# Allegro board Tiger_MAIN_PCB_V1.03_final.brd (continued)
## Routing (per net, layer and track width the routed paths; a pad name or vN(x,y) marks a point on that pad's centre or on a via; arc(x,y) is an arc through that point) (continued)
M_B_DQ<9>: length 61.9
  TOP w0.076: v2(206.19,48.98) 206.75,49.55 206.75,54.39 206.75,54.39 206.75,55.51 206.54,55.71 206.54,56.26 206.22,56.58 U1.AW35
  TOP w0.129: v2(232.86,20.03) 232.77,20.03 232.37,20.44 CN1.29
  LAY3 w0.076: v2(206.19,48.98) 205.77,48.56 205.77,44.45
  LAY3 w0.087: v2(232.86,20.03) 232.47,20.43 232.47,23.89 229.94,26.42 229.57,26.42 228.65,27.35 228.65,27.47 228.8,27.62 228.8,27.74 228.67,27.87 228.55,27.87 228.4,27.72 228.28,27.72 228.16,27.84 228.16,27.96 228.31,28.11 228.31,28.23 228.18,28.36 228.06,28.36 227.91,28.21 227.79,28.21 227.67,28.33 227.67,28.45 227.82,28.6 227.82,28.72 227.69,28.85 227.57,28.85 227.42,28.7 227.3,28.7 227.18,28.82 227.18,28.94 227.33,29.09 227.33,29.22 227.2,29.34 227.08,29.34 226.93,29.19 226.81,29.19 226.69,29.31 226.69,29.43 226.84,29.58 226.84,29.71 226.71,29.83 226.59,29.83 226.44,29.68 226.32,29.68 226.19,29.8 226.19,29.92 226.35,30.07 226.35,30.2 226.22,30.32 226.1,30.32 225.95,30.17 225.83,30.17 225.7,30.29 225.7,30.41 225.86,30.56 225.86,30.69 225.73,30.81 225.61,30.81 225.46,30.66 225.34,30.66 225.21,30.78 225.21,30.9 225.37,31.05 225.37,31.18 225.24,31.3 225.12,31.3 224.97,31.15 224.85,31.15 224.72,31.27 224.72,31.39 224.87,31.54 224.87,31.67 224.75,31.79 224.63,31.79 224.48,31.64 224.36,31.64 224.23,31.76 224.23,31.88 224.38,32.03 224.38,32.16 224.26,32.28 224.14,32.28 223.99,32.13 223.87,32.13 223.74,32.25 223.74,32.37 223.89,32.52 223.89,32.65 223.77,32.77 223.65,32.77 223.5,32.62 223.38,32.62 223.25,32.74 223.25,32.86 223.4,33.01 223.4,33.14 223.28,33.26 223.16,33.26 223.01,33.11 222.89,33.11 222.55,33.45 215.73,33.45 205.77,43.4 205.77,44.45
M_B_DQ<10>: length 61.2
  TOP w0.076: U1.AY33 204.99,55.92 204.72,55.65 204.72,55.3 204.67,55.2 204.61,55.06 204.56,54.97 204.56,54.6 204.69,54.48 204.69,54.48 204.74,54.42 204.74,54.1 204.58,53.94 204.58,51.01 204.02,50.44 204.02,50.44 203.9,50.32 203.9,46.89 v2(204.41,46.38)
  TOP w0.129: CN1.37 230.37,20.13 229.68,19.45 v2(229.36,19.45)
  LAY3 w0.076: v2(204.41,46.38) 204,45.97 204,45.23 203.64,44.87
  LAY3 w0.087: 203.64,44.87 203.64,41.51 206.69,38.46 206.69,37.85 206.83,37.7 206.94,37.7 207.1,37.86 207.22,37.86 207.34,37.73 207.34,37.61 207.2,37.47 207.2,37.34 207.32,37.21 207.45,37.21 207.66,37.43 207.78,37.43 207.91,37.31 207.91,37.18 207.69,36.97 207.69,36.85 207.82,36.72 207.94,36.72 208.15,36.94 208.27,36.94 208.4,36.82 208.4,36.69 208.18,36.48 208.18,36.36 208.31,36.23 208.43,36.23 208.64,36.45 208.76,36.45 208.89,36.33 208.89,36.2 208.67,35.99 208.67,35.87 208.8,35.74 208.92,35.74 209.13,35.96 209.25,35.96 209.38,35.84 209.38,35.71 209.16,35.5 209.16,35.38 209.29,35.25 209.41,35.25 209.62,35.47 209.74,35.47 209.87,35.35 209.87,35.22 209.65,35.01 209.65,34.89 209.78,34.76 209.9,34.76 210.11,34.98 210.24,34.98 210.36,34.85 210.36,34.73 210.14,34.52 210.14,34.4 213.68,30.86 221.57,30.86 228.96,23.46 228.96,19.85 v2(229.36,19.45)
M_B_DQ<11>: length 60.1
  TOP w0.076: U1.AW33 205.65,56.78 205.85,56.57 205.85,56.06 205.92,55.95 205.92,55.7 205.88,55.58 205.88,55.35 205.89,55.34 205.89,55.34 205.89,55.34 205.92,55.25 205.92,55.05 205.89,54.96 205.89,54.29 206.09,54.08 206.09,53.18 205.46,52.55 205.46,50.07 205.59,49.94 205.59,46.91 v2(204.41,45.73)
  TOP w0.129: v2(229.36,20.62) 229.37,20.62 CN1.41
  LAY3 w0.076: v2(204.41,45.73) 204.41,45.31 203.97,44.87
  LAY3 w0.087: v2(229.36,20.62) 229.49,20.74 229.49,21.77 229.41,21.85 229.37,21.85 229.28,21.94 229.28,22.11 229.37,22.2 229.41,22.2 229.49,22.29 229.49,22.46 229.41,22.55 229.37,22.55 229.28,22.63 229.28,22.81 229.37,22.89 229.41,22.89 229.49,22.98 229.49,23.43 221.74,31.19 214.52,31.19 214.18,31.53 214.06,31.53 213.84,31.31 213.72,31.31 213.59,31.43 213.59,31.55 213.81,31.77 213.81,31.89 213.69,32.02 213.57,32.02 213.35,31.8 213.23,31.8 213.1,31.92 213.1,32.04 213.32,32.26 213.32,32.38 213.2,32.51 213.08,32.51 212.86,32.29 212.74,32.29 212.61,32.41 212.61,32.53 212.83,32.75 212.83,32.87 212.71,33 212.59,33 212.37,32.78 212.25,32.78 212.12,32.9 212.12,33.02 212.34,33.24 212.34,33.36 212.22,33.49 212.1,33.49 211.88,33.27 211.76,33.27 211.63,33.39 211.63,33.51 211.85,33.73 211.85,33.85 211.73,33.98 211.61,33.98 211.39,33.76 211.27,33.76 211.14,33.88 211.14,34 211.36,34.22 211.36,34.34 211.24,34.47 211.12,34.47 210.9,34.25 210.78,34.25 210.65,34.37 210.65,34.49 210.87,34.71 210.87,34.83 203.97,41.74 203.97,44.87
M_B_DQ<12>: length 60
  TOP w0.076: v2(206.19,50.93) 205.79,51.32 205.79,52.41 206.42,53.04 206.42,54.25 206.42,54.72 U1.BB35
  TOP w0.129: CN1.24 233.61,15.81 232.51,16.92 v2(232.11,16.92)
  LAY3 w0.076: v2(206.19,50.93) 206.12,50.93 205.42,50.23 205.42,45.08 205.19,44.85 ; 231.2,23.35 231.2,21.32 231.82,20.69
  LAY3 w0.087: 231.82,20.69 231.82,18.41 231.91,18.32 232.79,18.32 232.87,18.24 232.87,18.06 232.79,17.98 231.91,17.98 231.82,17.89 231.82,17.06 231.97,16.92 v2(232.11,16.92) ; 231.2,23.35 231.2,23.91 222.33,32.77 215.45,32.77 205.19,43.04 205.19,44.85
M_B_DQ<13>: length 60.2
  TOP w0.076: U1.BA35 206.32,55.25 206.59,54.99 206.59,54.32 206.59,54.32 206.59,52.63 v2(206.19,52.23)
  TOP w0.129: CN1.28 232.61,15.25 v2(232.11,15.75)
  LAY3 w0.076: 204.88,44.88 205.25,45.25 205.25,51.29 v2(206.19,52.23)
  LAY3 w0.087: v2(232.11,15.75) 231.44,16.43 231.44,17.45 231.35,17.53 230.88,17.53 230.79,17.62 230.79,17.79 230.88,17.88 231.35,17.88 231.44,17.97 231.44,18.14 231.35,18.23 230.88,18.23 230.79,18.31 230.79,18.49 230.88,18.57 231.35,18.57 231.44,18.66 231.44,19.12 230.83,19.73 230.83,23.83 222.22,32.44 215.31,32.44 204.88,42.87 204.88,44.88
M_B_DQ<14>: length 60.4
  TOP w0.076: U1.BA33 204.99,55.33 204.85,55.18 204.85,55.18 204.85,55.18 204.73,54.93 204.73,54.67 204.91,54.49 204.91,54.03 204.77,53.89 204.77,50.64 v2(204.41,50.28)
  TOP w0.129: CN1.42 229.11,15.16 v2(229.11,15.16)
  LAY3 w0.076: 202.98,44.8 203.29,45.11 203.29,49.16 v2(204.41,50.28)
  LAY3 w0.087: v2(229.11,15.16) 228.52,15.16 228.21,15.48 228.21,23.32 221.33,30.2 213.31,30.2 204.78,38.73 204.78,38.85 204.95,39.02 204.95,39.15 204.83,39.27 204.7,39.27 204.53,39.1 204.41,39.1 204.29,39.22 204.29,39.34 204.46,39.51 204.46,39.64 204.34,39.76 204.21,39.76 204.04,39.59 203.92,39.59 203.8,39.71 203.8,39.83 203.97,40 203.97,40.13 203.85,40.25 203.72,40.25 203.55,40.08 203.43,40.08 202.98,40.53 202.98,44.8
M_B_DQ<15>: length 59.6
  TOP w0.076: v2(204.41,49.63) 204.93,50.15 204.93,53.82 205.07,53.96 205.07,54.61 204.99,54.69 U1.BB33
  TOP w0.129: v2(229.11,16.33) 229.39,16.33 230.11,15.61 CN1.38
  LAY3 w0.076: 203.34,44.88 203.61,45.16 203.61,48.83 v2(204.41,49.63)
  LAY3 w0.087: v2(229.11,16.33) 228.84,16.33 228.65,16.53 228.65,17.66 228.73,17.74 229.09,17.74 229.18,17.83 229.18,18 229.09,18.09 228.73,18.09 228.65,18.18 228.65,18.35 228.73,18.44 229.09,18.44 229.18,18.52 229.18,18.7 229.09,18.78 228.73,18.78 228.65,18.87 228.65,23.33 221.42,30.56 213.46,30.56 206.25,37.77 206.25,38.38 203.34,41.29 203.34,44.88
M_B_DQ<16>: length 51.4
  TOP w0.076: U1.AU40 v2(209.76,57.61)
  TOP w0.129: v2(194.62,15.75) 194.11,15.25 CN1.174
  LAY6 w0.076: 207.28,44.39 207.28,52.39 208.9,54.01 208.9,56.75 v2(209.76,57.61) ; 194.06,21.15 194.24,20.96
  LAY6 w0.087: 194.06,21.15 193.93,21.27 193.93,24.39 194.18,24.63 194.18,28.27 197.39,31.48 197.39,32.1 199.52,34.23 199.52,36.13 207.28,43.89 207.28,44.39 ; v2(194.62,15.75) 194.24,16.13 194.24,20.96
M_B_DQ<17>: length 52
  TOP w0.076: U1.AT40 v2(209.76,58.24)
  TOP w0.129: v2(194.86,20.03) 194.36,20.53 CN1.173
  LAY6 w0.076: v2(209.76,58.24) 209.76,58.12 210.11,57.77 210.11,56.8 209.15,55.83 209.15,53.95 207.57,52.37 207.57,44.23
  LAY6 w0.087: v2(194.86,20.03) 194.81,19.97 194.66,19.97 194.48,20.15 194.48,21.24 194.29,21.43 194.29,24.19 194.48,24.38 194.48,28.13 197.77,31.41 197.77,31.99 197.95,32.17 198.07,32.17 198.22,32.02 198.34,32.02 198.47,32.14 198.47,32.26 198.32,32.41 198.32,32.53 198.44,32.66 198.56,32.66 198.71,32.51 198.84,32.51 198.96,32.63 198.96,32.75 198.81,32.9 198.81,33.02 198.93,33.15 199.05,33.15 199.2,33 199.33,33 199.45,33.12 199.45,33.24 199.3,33.39 199.3,33.51 199.84,34.06 199.84,34.61 199.93,34.69 200.41,34.69 200.5,34.78 200.5,34.95 200.41,35.04 199.93,35.04 199.84,35.13 199.84,35.3 199.93,35.39 200.41,35.39 200.5,35.47 200.5,35.65 200.41,35.73 199.93,35.73 199.84,35.82 199.84,36.04 207.57,43.77 207.57,44.23
M_B_DQ<18>: length 53
  TOP w0.076: U1.AT37 v2(207.93,58.24)
  TOP w0.129: CN1.182 192.11,15.34 v2(191.11,16.34)
  LAY6 w0.076: v2(207.93,58.24) 207.93,58.13 207.57,57.77 207.57,56.05 207.12,55.6 207.12,53.92 205.43,52.23
  LAY6 w0.087: 205.43,52.23 205.43,43.91 197.94,36.42 197.94,34.95 191.83,28.84 191.83,21.48 191.63,21.28 191.63,18.18 191.54,18.1 191.33,18.1 191.24,18.01 191.24,17.84 191.33,17.75 191.54,17.75 191.63,17.66 191.63,16.85 v2(191.11,16.34)
M_B_DQ<19>: length 52.4
  TOP w0.076: U1.AU37 v2(207.93,57.59)
  TOP w0.129: CN1.186 v2(191.11,15.17)
  LAY6 w0.076: 205.73,52.28 207.29,53.84 207.29,55.39 207.93,56.03 v2(207.93,57.59)
  LAY6 w0.087: v2(191.11,15.17) 191.94,16 191.94,18.14 192.03,18.23 192.23,18.23 192.32,18.31 192.32,18.49 192.23,18.57 192.03,18.57 191.94,18.66 191.94,18.83 192.03,18.92 192.23,18.92 192.32,19.01 192.32,19.18 192.23,19.27 192.03,19.27 191.94,19.35 191.94,21.13 192.13,21.32 192.13,28.66 198.24,34.77 198.24,36.29 205.73,43.78 205.73,52.28
M_B_DQ<20>: length 52.7
  TOP w0.076: U1.AR40 v2(209.76,58.88)
  TOP w0.129: CN1.169 195.36,19.36 v2(194.86,18.86)
  LAY6 w0.076: v2(209.76,58.88) 210.14,58.5 210.14,57.99 210.28,57.85 210.28,56.64 209.76,56.12 209.76,53.22 208.37,51.83 208.37,46.11 207.88,45.63 207.88,44.29
  LAY6 w0.087: 207.88,44.29 207.88,43.64 200.81,36.57 200.81,34 200.35,33.55 200.23,33.55 200.07,33.7 199.94,33.7 199.82,33.58 199.82,33.46 199.98,33.3 199.98,33.18 194.8,28 194.8,21.6 195.26,21.14 195.26,18.53 195.15,18.42 194.84,18.42 194.71,18.55 194.71,18.71 v2(194.86,18.86)
M_B_DQ<21>: length 53.7
  TOP w0.076: U1.AP40 v2(209.76,59.51)
  TOP w0.129: v2(194.61,16.96) 195.11,16.46 CN1.170
  LAY6 w0.076: v2(209.76,59.51) 210.3,58.97 210.3,58.11 210.44,57.97 210.44,56.33 209.96,55.85 209.96,53.13 208.59,51.76 208.59,46.05 208.09,45.56 208.09,44.27
  LAY6 w0.087: 208.09,44.27 208.09,43.42 201.12,36.44 201.12,33.87 195.12,27.86 195.12,21.84 195.47,21.48 195.47,17.83 v2(194.61,16.96)
M_B_DQ<22>: length 54.5
  TOP w0.076: U1.AP37 v2(207.93,59.51)
  TOP w0.129: CN1.187 190.86,20.62 v2(190.86,20.62)
  LAY6 w0.076: 204.81,52.13 206.69,54 206.69,55.75 207.22,56.28 207.22,57.93 207.37,58.09 207.37,58.95 v2(207.93,59.51)
  LAY6 w0.087: v2(190.86,20.62) 190.86,22.59 190.95,22.68 191.09,22.68 191.18,22.76 191.18,22.94 191.09,23.02 190.95,23.02 190.86,23.11 190.86,23.28 190.95,23.37 191.09,23.37 191.18,23.46 191.18,23.63 191.09,23.72 190.95,23.72 190.86,23.8 190.86,23.98 190.95,24.06 191.09,24.06 191.18,24.15 191.18,24.32 191.09,24.41 190.95,24.41 190.86,24.49 190.86,24.67 190.95,24.75 191.09,24.75 191.18,24.84 191.18,25.01 191.09,25.1 190.95,25.1 190.86,25.19 190.86,25.36 190.95,25.45 191.09,25.45 191.18,25.53 191.18,25.71 191.09,25.79 190.95,25.79 190.86,25.88 190.86,26.05 190.95,26.14 191.09,26.14 191.18,26.23 191.18,26.4 191.09,26.49 190.95,26.49 190.86,26.57 190.86,26.75 190.95,26.83 191.09,26.83 191.18,26.92 191.18,27.09 191.09,27.18 190.95,27.18 190.86,27.27 190.86,27.44 190.95,27.53 191.09,27.53 191.18,27.61 191.18,27.79 191.09,27.87 190.95,27.87 190.86,27.96 190.86,28.13 190.95,28.22 191.09,28.22 191.18,28.31 191.18,28.48 191.09,28.57 190.95,28.57 190.86,28.65 190.86,29.32 191.16,29.62 191.29,29.62 191.44,29.47 191.56,29.47 191.69,29.59 191.69,29.71 191.53,29.87 191.53,29.99 191.65,30.11 191.78,30.11 191.93,29.96 192.05,29.96 192.18,30.08 192.18,30.2 192.02,30.36 192.02,30.48 192.14,30.6 192.27,30.6 192.42,30.45 192.55,30.45 192.67,30.57 192.67,30.69 192.51,30.85 192.51,30.97 192.63,31.09 192.76,31.09 192.91,30.94 193.04,30.94 193.16,31.06 193.16,31.18 193,31.34 193,31.46 196.96,35.42 196.96,35.6 197.04,35.69 197.19,35.69 197.27,35.77 197.27,35.95 197.19,36.03 197.04,36.03 196.96,36.12 196.96,36.3 204.81,44.16 204.81,52.13
M_B_DQ<23>: length 54.1
  TOP w0.076: U1.AR37 v2(207.93,58.88)
  TOP w0.129: CN1.183 191.86,19.85 191.47,19.45 v2(190.86,19.45)
  LAY6 w0.076: v2(207.93,58.88) 207.56,58.51 207.56,58.01 207.4,57.84 207.4,56.17 206.9,55.67 206.9,53.95 205.12,52.17
  LAY6 w0.087: v2(190.86,19.45) 191.3,19.88 191.3,21.55 191.51,21.76 191.51,28.98 193.97,31.44 193.97,31.56 193.83,31.7 193.83,31.82 193.95,31.94 194.07,31.94 194.21,31.8 194.33,31.8 194.46,31.93 194.46,32.05 194.32,32.19 194.32,32.31 194.44,32.43 194.56,32.43 194.7,32.29 194.82,32.29 194.95,32.42 194.95,32.54 194.81,32.68 194.81,32.8 194.93,32.92 195.05,32.92 195.19,32.78 195.31,32.78 195.44,32.91 195.44,33.03 195.3,33.17 195.3,33.29 195.42,33.41 195.54,33.41 195.68,33.27 195.81,33.27 195.93,33.4 195.93,33.52 195.79,33.66 195.79,33.78 195.91,33.9 196.03,33.9 196.17,33.76 196.3,33.76 196.42,33.89 196.42,34.01 196.28,34.15 196.28,34.27 196.4,34.39 196.53,34.39 196.66,34.25 196.79,34.25 196.91,34.38 196.91,34.5 196.77,34.64 196.77,34.76 196.89,34.88 197.02,34.88 197.1,34.79 197.33,34.79 197.63,35.1 197.63,36.55 205.12,44.04 205.12,52.17
M_B_DQ<24>: length 55.2
  TOP w0.076: v2(206.1,58.24) 205.92,58.38 U1.AT33
  TOP w0.129: v2(189.36,18.86) 189.87,19.36 CN1.191
  LAY6 w0.076: v2(206.1,58.24) 206.1,58.13 206.46,57.78 206.46,57.31 205.85,56.71 205.85,54.89 204.5,53.54 204.5,52.99 203.54,52.03
  LAY6 w0.087: v2(189.36,18.86) 189.75,18.86 189.96,19.07 189.96,20.98 189.8,21.14 189.8,30.08 192.97,33.25 192.97,34.23 193.19,34.46 193.31,34.46 193.62,34.15 193.74,34.15 193.86,34.28 193.86,34.4 193.56,34.7 193.56,34.82 193.68,34.95 193.8,34.95 194.11,34.64 194.23,34.64 194.35,34.77 194.35,34.89 194.05,35.19 194.05,35.31 194.17,35.44 194.29,35.44 194.6,35.13 194.72,35.13 194.84,35.26 194.84,35.38 194.54,35.68 194.54,35.8 194.66,35.93 194.78,35.93 195.09,35.62 195.21,35.62 195.33,35.75 195.33,35.87 195.03,36.17 195.03,36.29 198.72,39.99 199.27,39.99 203.54,44.25 203.54,52.03
M_B_DQ<25>: length 54.7
  TOP w0.076: v2(206.1,57.61) 205.92,57.74 U1.AU33
  TOP w0.129: CN1.195 188.87,20.53 v2(189.36,20.03)
  LAY6 w0.076: 203.32,52.1 204.27,53.06 204.27,53.64 205.57,54.94 205.57,56.75 206.1,57.28 v2(206.1,57.61)
  LAY6 w0.087: 203.32,52.1 203.32,44.45 199.23,40.36 198.65,40.36 192.25,33.96 192.25,33.84 192.55,33.54 192.55,33.41 192.43,33.29 192.31,33.29 192.01,33.59 191.88,33.59 191.76,33.47 191.76,33.35 192.11,32.99 192.11,32.87 191.99,32.75 191.87,32.75 191.52,33.1 191.39,33.1 191.27,32.98 191.27,32.86 191.62,32.5 191.62,32.38 191.5,32.26 191.38,32.26 191.03,32.61 190.9,32.61 190.78,32.49 190.78,32.37 191.13,32.01 191.13,31.89 191.01,31.77 190.89,31.77 190.54,32.12 190.41,32.12 190.29,32 190.29,31.88 190.64,31.52 190.64,31.4 190.52,31.28 190.4,31.28 190.05,31.63 189.92,31.63 189.8,31.51 189.8,31.39 190.15,31.03 190.15,30.91 190.03,30.79 189.91,30.79 189.55,31.14 189.43,31.14 189.26,30.97 189.26,21.25 189.74,20.77 189.74,20.41 v2(189.36,20.03)
M_B_DQ<26>: length 53.7
  TOP w0.076: U1.AU30 v2(204.28,57.61)
  TOP w0.129: CN1.208 v2(185.61,15.17)
  LAY6 w0.076: v2(204.28,57.61) 204.28,57.08 203.99,56.79 203.99,56.42 204.4,56.01 204.4,55.52 203.57,54.69 203.57,53.78 202.06,52.27
  LAY6 w0.087: v2(185.61,15.17) 186.57,16.13 186.57,17.22 187.43,18.08 187.43,21.09 188.02,21.67 188.02,22.27 187.93,22.36 187.77,22.36 187.69,22.45 187.69,22.62 187.77,22.71 187.93,22.71 188.02,22.79 188.02,22.97 187.93,23.05 187.77,23.05 187.69,23.14 187.69,23.31 187.77,23.4 187.93,23.4 188.02,23.49 188.02,31.49 197.95,41.42 198.53,41.42 202.06,44.95 202.06,52.27
M_B_DQ<27>: length 54.6
  TOP w0.076: U1.AT30 v2(204.28,58.24)
  TOP w0.129: CN1.204 186.61,15.6 185.88,16.34 v2(185.61,16.34)
  LAY6 w0.076: v2(204.28,58.24) 204.28,58.14 203.76,57.63 203.76,55.39 203.31,54.94 203.31,53.81 201.87,52.37
  LAY6 w0.087: 201.87,52.37 201.87,45.03 198.6,41.77 197.86,41.77 187.7,31.61 187.7,24.02 187.1,23.43 187.1,22.17 187.19,22.08 187.49,22.08 187.57,22 187.57,21.82 187.49,21.74 187.19,21.74 187.1,21.65 187.1,18.21 186.3,17.41 186.3,16.89 185.75,16.34 v2(185.61,16.34)
M_B_DQ<28>: length 55.9
  TOP w0.076: v2(206.1,58.88) 205.92,59.02 U1.AR33
  TOP w0.129: CN1.190 190.11,16.42 v2(189.61,16.92)
  LAY6 w0.076: v2(206.1,58.88) 206.19,58.96 206.42,58.96 206.46,58.92 206.46,58.03 206.65,57.84 206.65,57.21 206.04,56.6 206.04,54.8 204.73,53.49 204.73,52.94 203.74,51.95
  LAY6 w0.087: v2(189.61,16.92) 189.71,16.82 190.07,16.82 190.18,16.93 190.18,17.29 190.09,17.38 189.66,17.38 189.58,17.47 189.58,17.64 189.66,17.73 190.09,17.73 190.18,17.81 190.18,17.99 190.09,18.07 189.66,18.07 189.58,18.16 189.58,18.33 189.66,18.42 190.09,18.42 190.18,18.51 190.18,29.92 195.76,35.51 195.76,36.19 203.74,44.17 203.74,51.95
M_B_DQ<29>: length 56.8
  TOP w0.076: v2(206.1,59.51) 205.92,59.66 U1.AP33
  TOP w0.129: v2(189.61,15.75) 189.11,15.25 CN1.194
  LAY6 w0.076: v2(206.1,59.51) 206.45,59.51 206.65,59.32 206.65,58.09 206.87,57.87 206.87,57.17 206.23,56.54 206.23,54.68 205.01,53.46 205.01,52.92 204.48,52.38 204.48,51.02 203.98,50.53
  LAY6 w0.087: 203.98,50.53 203.98,44.07 196.07,36.16 196.07,35.38 190.48,29.8 190.48,15.97 190.65,15.81 190.65,14.82 190.53,14.7 190.28,14.7 190.15,14.83 190.15,15.58 189.97,15.75 v2(189.61,15.75)
M_B_DQ<30>: length 54.9
  TOP w0.076: U1.AR30 v2(204.28,58.88)
  TOP w0.129: v2(186.36,18.86) 186.87,19.36 CN1.203
  LAY6 w0.076: v2(204.28,58.88) 204.04,58.88 203.89,58.74 203.89,58 203.59,57.69 203.59,55.5 202.51,54.43 202.51,53.31 201.64,52.45
  LAY6 w0.087: v2(186.36,18.86) 186.77,19.27 186.77,20.98 186.64,21.11 186.64,23.6 187.34,24.3 187.34,26.96 186.64,27.66 186.64,29.13 186.73,29.21 187.21,29.21 187.29,29.3 187.29,29.47 187.21,29.56 186.73,29.56 186.64,29.65 186.64,29.82 186.73,29.91 187.21,29.91 187.29,29.99 187.29,30.17 187.21,30.25 186.73,30.25 186.64,30.34 186.64,31 197.8,42.15 198.66,42.15 201.64,45.13 201.64,52.45
M_B_DQ<31>: length 55.9
  TOP w0.076: U1.AP30 v2(204.28,59.51)
  TOP w0.129: v2(186.36,20.03) 185.87,20.53 CN1.207
  LAY6 w0.076: v2(204.28,59.51) 203.73,58.96 203.73,58.07 203.4,57.75 203.4,55.69 202.33,54.62 202.33,53.46 201.39,52.52
  LAY6 w0.087: v2(186.36,20.03) 186,20.4 186,24.3 186.08,24.39 186.66,24.39 186.75,24.48 186.75,24.65 186.66,24.74 186.08,24.74 186,24.82 186,25 186.08,25.08 186.68,25.08 186.77,25.17 186.77,25.34 186.68,25.43 186.08,25.43 186,25.52 186,25.69 186.08,25.77 186.68,25.77 186.77,25.86 186.77,26.03 186.68,26.12 186.08,26.12 186,26.21 186,26.38 186.08,26.47 186.68,26.47 186.77,26.55 186.77,26.73 186.68,26.81 186.08,26.81 186,26.9 186,30.82 197.63,42.45 198.61,42.45 201.39,45.23 201.39,52.52
M_B_DQ<32>: length 59.4
  TOP w0.076: v2(202.53,46.39) 203.64,47.5 203.64,53.11 203.95,53.43 203.95,53.54 203.95,53.54 203.95,54.09 203.95,54.1 203.95,54.43 204.13,54.6 204.13,54.97 204.11,55 203.96,55.37 203.96,55.65 203.69,55.92 U1.AY31
  TOP w0.129: v2(227.61,16.92) 228.11,16.42 CN1.46
  LAY3 w0.076: 201.86,44.54 202.53,45.22 v2(202.53,46.39)
  LAY3 w0.087: 201.86,44.54 201.86,40.06 212.85,29.07 220.57,29.07 225.57,24.07 225.57,21.36 226.08,20.85 226.08,18.69 226.5,18.27 226.62,18.27 226.79,18.44 226.91,18.44 227.04,18.32 227.04,18.19 226.87,18.02 226.87,17.9 227.61,17.15 v2(227.61,16.92)
M_B_DQ<33>: length 60
  TOP w0.076: v2(202.53,52.23) 202.51,52.26 202.51,54.15 202.8,54.44 202.8,54.97 202.79,55 202.75,55.08 202.75,55.2 202.82,55.41 202.82,55.56 202.76,55.72 202.76,55.9 202.78,55.95 202.78,56.52 203.04,56.78 U1.AW31
  TOP w0.129: v2(227.37,20.62) CN1.49
  LAY3 w0.076: v2(202.53,52.23) 202.89,51.87 202.89,48.24 203.09,48.04 203.09,45.3 202.5,44.7 202.5,43.32
  LAY3 w0.087: 202.5,43.32 202.5,40.33 213.12,29.7 220.85,29.7 227.18,23.36 227.18,23.09 227.09,23.01 226.29,23.01 226.21,22.92 226.21,22.75 226.3,22.65 227.42,22.65 227.5,22.56 227.5,22.39 227.42,22.3 226.28,22.3 226.21,22.23 226.21,22.05 226.3,21.95 227.42,21.95 227.5,21.87 227.5,21.69 227.42,21.61 226.52,21.61 226.41,21.49 226.41,21.32 226.49,21.23 227.32,21.23 227.37,21.19 v2(227.37,20.62)
M_B_DQ<34>: length 59
  TOP w0.076: v2(202.53,51.58) 202.14,51.97 202.14,52.45 202.34,52.65 202.34,54.21 202.64,54.51 202.64,54.93 202.58,55.05 202.58,55.19 202.64,55.42 202.64,55.55 202.57,55.77 202.57,56.02 U1.AY29
  TOP w0.129: CN1.63 v2(223.86,20.62)
  LAY3 w0.076: v2(202.53,51.58) 201.49,50.54 201.49,45.22 200.46,44.19
  LAY3 w0.087: 200.46,44.19 200.46,39.11 212.63,26.95 214.95,26.95 215.52,27.52 215.86,27.52 215.95,27.43 215.95,26.97 216.04,26.88 216.21,26.88 216.3,26.97 216.3,27.43 216.38,27.52 216.56,27.52 216.64,27.43 216.64,26.97 216.73,26.88 216.9,26.88 216.99,26.97 216.99,27.43 217.08,27.52 217.25,27.52 217.33,27.43 217.33,26.97 217.42,26.88 217.59,26.88 217.68,26.97 217.68,27.43 217.77,27.52 217.94,27.52 218.03,27.43 218.03,26.97 218.11,26.88 218.29,26.88 218.37,26.97 218.37,27.43 218.46,27.52 218.63,27.52 218.72,27.43 218.72,26.97 218.81,26.88 218.98,26.88 219.07,26.97 219.07,27.43 219.15,27.52 219.83,27.52 224.24,23.11 224.24,22.49 224.15,22.41 224.12,22.41 224.03,22.32 224.03,22.15 224.12,22.06 224.15,22.06 224.24,21.97 224.24,21.8 224.15,21.71 224.12,21.71 224.03,21.63 224.03,21.45 224.12,21.37 224.15,21.37 224.24,21.28 224.24,20.99 v2(223.86,20.62)
M_B_DQ<35>: length 59.6
  TOP w0.076: U1.AW29 202.47,56.56 202.16,56.25 202.16,55.7 201.94,55.48 201.94,54.53 201.85,54.44 201.85,52.86 201.64,52.65 201.64,48.38 v2(200.93,47.67)
  TOP w0.129: v2(223.86,19.45) 224.1,19.45 224.86,20.22 CN1.59
  LAY3 w0.076: v2(200.93,47.67) 201.31,47.29 201.31,45.31 201.1,45.09
  LAY3 w0.087: v2(223.86,19.45) 223.79,19.37 223.6,19.37 223.46,19.51 223.46,21.05 223.73,21.32 223.73,23.1 223.44,23.39 222.84,23.39 222.72,23.51 222.72,23.63 222.89,23.81 222.89,23.93 222.77,24.05 222.65,24.05 222.47,23.88 222.35,23.88 222.23,24 222.23,24.12 222.4,24.3 222.4,24.42 222.28,24.54 222.16,24.54 221.98,24.37 221.86,24.37 221.74,24.49 221.74,24.61 221.91,24.79 221.91,24.91 221.79,25.04 221.67,25.04 221.49,24.86 221.37,24.86 221.25,24.98 221.25,25.1 221.42,25.28 221.42,25.4 221.3,25.53 221.18,25.53 221,25.35 220.88,25.35 220.76,25.47 220.76,25.59 220.93,25.77 220.93,25.89 220.25,26.58 212.55,26.58 200.13,38.99 200.13,44.13 201.1,45.09
M_B_DQ<36>: length 58
  TOP w0.076: U1.BB31 203.62,54.75 203.62,53.96 203.62,53.61 203.31,53.3 203.31,49.11 v2(202.53,48.33)
  TOP w0.129: v2(227.37,19.45) 227.7,19.45 228.37,20.11 CN1.45
  LAY3 w0.076: v2(202.53,48.33) 202.91,47.95 202.91,45.36 202.18,44.63 202.18,43.32
  LAY3 w0.087: v2(227.37,19.45) 227.44,19.38 227.44,19.07 227.16,18.79 226.51,18.79 226.4,18.91 226.4,19.27 226.48,19.36 226.86,19.36 226.94,19.44 226.94,19.62 226.86,19.7 226.48,19.7 226.4,19.79 226.4,19.96 226.48,20.05 226.86,20.05 226.94,20.14 226.94,20.31 226.86,20.4 226.48,20.4 226.4,20.48 226.4,20.86 225.9,21.36 225.9,24.2 220.72,29.38 213,29.38 202.18,40.2 202.18,43.32
M_B_DQ<37>: length 58.4
  TOP w0.076: v2(202.53,47.68) 203.47,48.62 203.47,53.19 203.79,53.5 203.79,53.61 203.79,54.03 203.79,54.03 203.79,54.5 203.96,54.67 203.96,54.93 203.84,55.18 203.84,55.18 203.84,55.18 203.69,55.33 U1.BA31
  TOP w0.129: CN1.50 227.11,15.25 v2(227.61,15.75)
  LAY3 w0.076: 201.54,44.47 202.33,45.26 202.33,46.06 202.15,46.24 202.15,47.3 v2(202.53,47.68)
  LAY3 w0.087: v2(227.61,15.75) 227.23,16.13 227.23,17.12 225.82,18.52 225.82,20.8 225.25,21.37 225.25,23.94 220.44,28.75 212.72,28.75 201.54,39.93 201.54,44.47
M_B_DQ<38>: length 58.2
  TOP w0.076: U1.BA29 202.37,55.25 202.1,54.98 202.1,54.44 202.01,54.35 202.01,52.79 201.81,52.58 201.81,47.84 v2(200.93,46.96)
  TOP w0.129: CN1.62 224.11,15.25 v2(224.61,15.75)
  LAY3 w0.076: 199.51,43.99 200.54,45.03 200.54,46.57 v2(200.93,46.96)
  LAY3 w0.087: v2(224.61,15.75) 224.11,16.25 224.11,17.8 222.83,19.08 222.83,21.36 222.74,21.45 222.47,21.45 222.38,21.53 222.38,21.71 222.47,21.79 222.74,21.79 222.83,21.88 222.83,22.26 219.15,25.94 212.28,25.94 199.51,38.72 199.51,43.99
M_B_DQ<39>: length 57.3
  TOP w0.076: v2(200.93,45.64) 201.93,46.64 201.93,47.3 201.97,47.34 201.97,52.52 202.18,52.72 202.18,54.28 202.37,54.48 U1.BB29
  TOP w0.129: v2(224.61,16.92) 225.11,16.42 CN1.58
  LAY3 w0.076: v2(200.93,45.64) 200.93,45.17 199.81,44.05
  LAY3 w0.087: 199.81,44.05 199.81,38.86 212.42,26.26 219.54,26.26 219.78,26.01 219.91,26.01 220.07,26.18 220.19,26.18 220.32,26.05 220.32,25.93 220.15,25.77 220.15,25.64 223.15,22.65 223.15,19.37 224.61,17.91 v2(224.61,16.92)
M_B_DQ<40>: length 61.1
  TOP w0.076: v2(200.93,50.28) 200.37,50.84 200.37,52.72 201.18,53.53 201.18,54.56 201.07,54.67 201.07,54.93 201.11,55.02 201.11,55.03 201.11,55.28 201.07,55.37 201.07,55.57 201.14,55.76 201.14,56.02 U1.AY27
  TOP w0.129: v2(222.37,18.86) 222.86,19.36 CN1.67
  LAY3 w0.076: 198.82,43.83 200.17,45.19 200.17,49.52 v2(200.93,50.28)
  LAY3 w0.087: 198.82,43.83 198.82,38.19 212.6,24.41 213.46,24.41 213.54,24.33 213.54,23.95 213.62,23.86 213.8,23.86 213.88,23.95 213.88,24.31 213.98,24.41 214.16,24.41 214.23,24.33 214.23,23.95 214.32,23.86 214.49,23.86 214.58,23.95 214.58,24.31 214.68,24.41 218.75,24.41 218.99,24.17 219.11,24.17 219.37,24.43 219.49,24.43 219.61,24.3 219.61,24.18 219.36,23.92 219.36,23.8 219.66,23.5 219.78,23.5 220.07,23.79 220.19,23.79 220.32,23.66 220.32,23.54 220.03,23.25 220.03,23.13 220.15,23.01 220.27,23.01 220.56,23.3 220.69,23.3 220.81,23.17 220.81,23.05 220.52,22.76 220.52,22.64 220.64,22.52 220.76,22.52 221.05,22.81 221.18,22.81 221.3,22.68 221.3,22.56 221.01,22.27 221.01,22.15 221.7,21.46 221.7,19.53 v2(222.37,18.86)
M_B_DQ<41>: length 61.6
  TOP w0.076: U1.AW27 201.24,56.58 201.56,56.26 201.56,55.71 201.77,55.51 201.77,54.6 201.68,54.51 201.68,52.93 201.48,52.72 201.48,49.53 v2(200.93,48.98)
  TOP w0.129: v2(222.37,20.03) 222.05,20.03 221.86,20.22 CN1.71
  LAY3 w0.076: 199.12,43.86 200.34,45.08 200.34,48.39 v2(200.93,48.98)
  LAY3 w0.087: v2(222.37,20.03) 221.98,20.42 221.98,22.55 219.58,24.94 218.87,24.94 218.68,25.13 218.68,25.37 218.6,25.46 218.42,25.46 218.34,25.37 218.34,25.03 218.25,24.94 218.08,24.94 217.99,25.03 217.99,25.37 217.9,25.46 217.73,25.46 217.64,25.37 217.64,25.03 217.56,24.94 217.38,24.94 217.3,25.03 217.3,25.37 217.21,25.46 217.04,25.46 216.95,25.37 216.95,25.03 216.86,24.94 216.69,24.94 216.6,25.03 216.6,25.37 216.52,25.46 216.34,25.46 216.26,25.37 216.26,25.03 216.17,24.94 216,24.94 215.91,25.03 215.91,25.37 215.82,25.46 215.65,25.46 215.56,25.37 215.56,25.03 215.48,24.94 215.3,24.94 215.22,25.03 215.22,25.37 215.13,25.46 214.96,25.46 214.87,25.37 214.87,25.03 214.78,24.94 214.61,24.94 214.53,25.03 214.53,25.37 214.44,25.46 214.27,25.46 214.18,25.37 214.18,25.03 214.09,24.94 213.92,24.94 213.83,25.03 213.83,25.37 213.75,25.46 213.57,25.46 213.49,25.37 213.49,25.03 213.4,24.94 213.23,24.94 213.14,25.03 213.14,25.37 213.05,25.46 212.88,25.46 212.79,25.37 212.79,25.03 212.71,24.94 212.49,24.94 199.12,38.31 199.12,43.86
M_B_DQ<42>: length 60.8
  TOP w0.076: v2(198.95,46.38) 198.55,46.77 198.55,50.36 199.36,51.16 199.36,53.21 199.36,53.21 199.56,53.41 199.56,54.92 199.74,55.3 199.74,55.85 U1.AY25
  TOP w0.129: CN1.83 218.86,20.22 219.63,19.45 v2(219.86,19.45)
  LAY3 w0.087: v2(219.86,19.45) 219.71,19.45 219.43,19.73 219.43,20.86 218.32,21.96 211.15,21.96 210.42,22.69 210.42,22.81 210.58,22.98 210.58,23.1 210.46,23.22 210.34,23.22 210.17,23.06 210.05,23.06 209.93,23.18 209.93,23.3 210.09,23.47 210.09,23.59 209.97,23.71 209.85,23.71 209.68,23.55 209.56,23.55 209.44,23.67 209.44,23.79 209.6,23.96 209.6,24.08 209.48,24.2 209.36,24.2 209.19,24.04 209.07,24.04 208.95,24.16 208.95,24.28 209.11,24.45 209.11,24.57 208.99,24.69 208.87,24.69 208.7,24.53 208.58,24.53 208.46,24.65 208.46,24.78 208.62,24.94 208.62,25.06 208.5,25.18 208.37,25.18 208.21,25.02 208.09,25.02 207.97,25.14 207.97,25.27 208.13,25.43 208.13,25.55 208.01,25.67 207.88,25.67 207.72,25.51 207.6,25.51 207.48,25.63 207.48,25.76 207.64,25.92 207.64,26.04 207.52,26.16 207.39,26.16 207.23,26 207.11,26 206.99,26.12 206.99,26.25 207.15,26.41 207.15,26.53 207.03,26.65 206.9,26.65 206.74,26.49 206.62,26.49 206.5,26.61 206.5,26.74 206.66,26.9 206.66,27.02 206.54,27.14 206.41,27.14 206.25,26.98 206.13,26.98 196.72,36.39 196.72,44.15 v2(198.95,46.38)
M_B_DQ<43>: length 61.3
  TOP w0.076: U1.AW25 200.67,56.78 200.87,56.57 200.87,56.06 200.94,55.95 200.94,55.7 200.9,55.58 200.9,55.35 200.9,55.34 200.91,55.34 200.91,55.34 200.94,55.25 200.94,55.05 200.91,54.96 200.91,54.6 201.02,54.49 201.02,53.6 200.21,52.79 200.21,50.64 200.38,50.47 200.38,47.16 v2(198.95,45.73)
  TOP w0.129: CN1.79 v2(219.86,20.62)
  LAY3 w0.087: v2(198.95,45.73) 197.08,43.86 197.08,37.18 199.5,34.76 199.5,34.64 199.27,34.41 199.27,34.28 199.39,34.16 199.51,34.16 199.75,34.4 199.87,34.4 199.99,34.27 199.99,34.15 199.76,33.92 199.76,33.79 199.88,33.67 200,33.67 200.24,33.91 200.36,33.91 200.48,33.78 200.48,33.66 200.25,33.43 200.25,33.3 200.37,33.18 200.49,33.18 200.73,33.41 200.85,33.41 200.97,33.29 200.97,33.17 200.74,32.94 200.74,32.81 200.86,32.69 200.98,32.69 201.22,32.92 201.34,32.92 201.46,32.8 201.46,32.68 201.23,32.45 201.23,32.32 201.35,32.2 201.48,32.2 201.71,32.43 201.83,32.43 201.95,32.31 201.95,32.19 201.72,31.96 201.72,31.83 201.84,31.71 201.97,31.71 202.2,31.94 202.32,31.94 202.44,31.82 202.44,31.7 202.21,31.47 202.21,31.34 202.33,31.22 202.46,31.22 202.69,31.45 202.81,31.45 202.93,31.33 202.93,31.21 202.7,30.98 202.7,30.85 202.82,30.73 202.95,30.73 203.18,30.96 203.3,30.96 203.42,30.84 203.42,30.72 203.19,30.49 203.19,30.36 203.31,30.24 203.44,30.24 203.67,30.47 203.79,30.47 203.91,30.35 203.91,30.23 203.68,30 203.68,29.87 203.8,29.75 203.93,29.75 204.09,29.92 204.35,29.92 211.99,22.27 218.32,22.27 219.73,20.86 219.73,20.75 v2(219.86,20.62)
M_B_DQ<44>: length 59.3
  TOP w0.076: v2(200.93,50.93) 200.54,51.32 200.54,52.65 201.35,53.46 201.35,54.81 U1.BB27
  TOP w0.129: CN1.66 v2(223.11,15.16)
  LAY3 w0.076: v2(200.93,50.93) 200,50.01 200,45.27 198.51,43.78
  LAY3 w0.087: 198.51,43.78 198.51,38.07 213.09,23.49 214.84,23.49 214.93,23.58 214.93,24 215.02,24.09 215.19,24.09 215.28,24 215.28,23.58 215.36,23.49 215.54,23.49 215.62,23.58 215.62,24 215.71,24.09 215.88,24.09 215.97,24 215.97,23.69 216.06,23.6 216.23,23.6 216.32,23.69 216.32,24 216.4,24.09 218.61,24.09 221.41,21.29 221.41,19.16 223.55,17.01 223.55,15.4 223.32,15.16 v2(223.11,15.16)
M_B_DQ<45>: length 59.9
  TOP w0.076: v2(200.93,52.23) 200.93,52.81 201.51,53.4 201.51,54.58 201.61,54.67 201.61,54.99 201.34,55.25 U1.BA27
  TOP w0.129: v2(223.11,16.33) 222.82,16.33 222.11,15.63 CN1.70
  LAY3 w0.076: v2(200.93,52.23) 199.84,51.14 199.84,45.4 198.21,43.77
  LAY3 w0.087: v2(223.11,16.33) 222.75,16.7 222.75,17.41 221.08,19.08 221.08,21 218.46,23.61 218.46,23.68 218.38,23.77 218.2,23.77 218.12,23.68 218.12,23.34 218.03,23.25 217.86,23.25 217.77,23.34 217.77,23.68 217.68,23.77 217.51,23.77 217.42,23.68 217.42,23.34 217.34,23.25 217.16,23.25 217.08,23.34 217.08,23.68 216.99,23.77 216.82,23.77 216.73,23.68 216.73,23.34 216.64,23.25 212.9,23.25 198.21,37.94 198.21,43.77
M_B_DQ<46>: length 59.9
  TOP w0.076: v2(198.95,50.23) 199.52,50.8 199.52,53.14 199.73,53.34 199.73,54.88 199.86,55.18 200.01,55.33 U1.BA25
  TOP w0.129: v2(219.11,15.75) 218.62,15.25 CN1.84
  LAY3 w0.087: v2(219.11,15.75) 218.39,15.75 218,16.14 218,16.28 218.09,16.36 218.38,16.36 218.47,16.45 218.47,16.62 218.38,16.71 218.07,16.71 217.99,16.8 217.99,16.97 218.07,17.06 218.38,17.06 218.47,17.14 218.47,17.32 218.38,17.4 218.07,17.4 217.99,17.49 217.99,19.1 218.78,19.89 218.78,20.72 218.18,21.31 210.8,21.31 196.11,36.01 196.11,44.16 197.99,46.04 197.99,49.27 v2(198.95,50.23)
M_B_DQ<47>: length 59
  TOP w0.076: U1.BB25 200.01,54.6 200,54.59 199.89,54.48 199.89,53.27 199.71,53.09 199.69,53.07 199.69,50.37 v2(198.95,49.63)
  TOP w0.129: CN1.80 219.62,16.42 v2(219.11,16.92)
  LAY3 w0.087: v2(219.11,16.92) 219.12,16.92 219.12,17.8 219.03,17.89 218.46,17.89 218.37,17.98 218.37,18.15 218.46,18.24 219.06,18.24 219.15,18.32 219.15,18.5 219.06,18.58 218.46,18.58 218.37,18.67 218.37,18.84 218.46,18.93 219.03,18.93 219.12,19.02 219.12,20.72 218.18,21.66 210.96,21.66 196.42,36.2 196.42,44.16 198.27,46.01 198.27,48.95 v2(198.95,49.63)
M_B_DQ<48>: length 56.9
  TOP w0.076: U1.AU27 v2(202.45,57.59)
  TOP w0.129: v2(184.11,15.75) 183.61,15.25 CN1.216
  LAY6 w0.076: 199.46,52.03 201.48,54.05 201.48,54.96 202.66,56.14 202.66,57.38 v2(202.45,57.59)
  LAY6 w0.087: 199.46,52.03 199.46,45.55 197.85,43.94 196.86,43.94 183.61,30.69 183.61,23.8 182.65,22.83 182.65,22.57 182.73,22.49 183.34,22.49 183.43,22.4 183.43,22.23 183.34,22.14 182.73,22.14 182.65,22.05 182.65,21.88 182.73,21.79 183.36,21.79 183.44,21.71 183.44,21.54 183.36,21.45 182.73,21.45 182.65,21.36 182.65,18 183.51,17.14 183.51,16.36 v2(184.11,15.75)
M_B_DQ<49>: length 57.6
  TOP w0.076: U1.AT27 v2(202.45,58.24)
  TOP w0.129: CN1.212 184.61,16.42 v2(184.11,16.92)
  LAY6 w0.076: 199.65,51.96 201.73,54.05 201.73,54.94 202.84,56.04 202.84,57.7 202.45,58.09 v2(202.45,58.24)
  LAY6 w0.087: v2(184.11,16.92) 184.11,17.32 184.2,17.4 184.95,17.4 185.03,17.49 185.03,17.66 184.95,17.75 184.01,17.75 183.9,17.85 183.9,18.03 183.97,18.09 184.95,18.09 185.03,18.18 185.03,18.35 184.95,18.44 184.05,18.44 183.93,18.56 183.93,30.56 197.04,43.67 197.85,43.67 199.65,45.47 199.65,51.96
M_B_DQ<50>: length 55.9
  TOP w0.076: U1.AT25 v2(201.53,58.24)
  TOP w0.129: CN1.229 v2(180.36,20.62)
  LAY6 w0.076: 197.33,51.25 200.06,53.98 200.06,54.81 201.15,55.9 201.15,57.73 201.53,58.11 v2(201.53,58.24)
  LAY6 w0.087: 197.33,51.25 197.33,46.82 190.03,39.52 189.13,39.52 188.63,39.01 188.63,38.06 186.42,35.86 186.3,35.86 186.15,36.01 186.02,36.01 185.9,35.89 185.9,35.77 186.06,35.61 186.06,35.49 185.93,35.37 185.81,35.37 185.65,35.52 185.53,35.52 185.41,35.4 185.41,35.28 185.57,35.12 185.57,35 185.44,34.88 185.32,34.88 185.16,35.03 185.04,35.03 184.92,34.91 184.92,34.79 185.08,34.63 185.08,34.51 184.95,34.39 184.83,34.39 184.67,34.54 184.55,34.54 184.43,34.42 184.43,34.3 184.59,34.14 184.59,34.02 184.46,33.9 184.34,33.9 184.18,34.05 184.06,34.05 183.94,33.93 183.94,33.81 184.1,33.65 184.1,33.53 183.97,33.41 183.85,33.41 183.69,33.56 183.57,33.56 183.45,33.44 183.45,33.32 183.61,33.16 183.61,33.04 183.48,32.91 183.36,32.91 183.2,33.07 183.08,33.07 182.96,32.95 182.96,32.83 183.12,32.67 183.12,32.55 182.99,32.42 182.87,32.42 182.71,32.58 182.59,32.58 182.47,32.46 182.47,32.34 182.63,32.18 182.63,32.06 182.5,31.93 182.38,31.93 182.22,32.09 182.1,32.09 181.98,31.97 181.98,31.85 182.14,31.69 182.14,31.57 182.01,31.44 181.89,31.44 181.73,31.6 181.61,31.6 181.49,31.48 181.49,31.36 181.65,31.2 181.65,31.08 181.52,30.95 181.4,30.95 181.24,31.11 181.12,31.11 181,30.99 181,30.87 181.15,30.71 181.15,30.59 181.03,30.46 180.91,30.46 180.75,30.62 180.63,30.62 180.51,30.5 180.51,30.38 180.66,30.22 180.66,30.1 180.36,29.8 v2(180.36,20.62)
M_B_DQ<51>: length 55.4
  TOP w0.076: U1.AU25 v2(201.53,57.61)
  TOP w0.129: v2(180.36,19.45) 180.59,19.45 181.36,20.22 CN1.225
  LAY6 w0.076: 197.52,51.18 200.26,53.92 200.26,54.75 201.34,55.82 201.34,57.41 v2(201.53,57.61)
  LAY6 w0.087: v2(180.36,19.45) 180.48,19.45 180.82,19.79 180.82,24.62 181.51,25.32 181.51,26.27 181.43,26.35 181.05,26.35 180.97,26.44 180.97,26.61 181.05,26.7 181.43,26.7 181.51,26.78 181.51,26.96 181.43,27.04 181.05,27.04 180.97,27.13 180.97,27.3 181.05,27.39 181.43,27.39 181.51,27.48 181.51,27.65 181.43,27.74 181.05,27.74 180.97,27.82 180.97,28 181.05,28.08 181.43,28.08 181.51,28.17 181.51,28.34 181.43,28.43 181.05,28.43 180.97,28.52 180.97,28.69 181.05,28.78 181.43,28.78 181.51,28.86 181.51,29.04 181.43,29.12 181.05,29.12 180.97,29.21 180.97,29.38 181.05,29.47 181.43,29.47 181.51,29.56 181.51,30.46 189.01,37.96 189.01,38.73 189.4,39.12 189.9,39.12 197.52,46.74 197.52,51.18
M_B_DQ<52>: length 57.9
  TOP w0.076: U1.AP27 v2(202.45,59.51)
  TOP w0.129: v2(184.87,19.45) 184.62,19.45 183.87,20.2 CN1.215
  LAY6 w0.087: v2(184.87,19.45) 184.81,19.45 184.48,19.77 184.48,21.11 184.71,21.34 184.71,23.43 184.63,23.51 184.34,23.51 184.26,23.6 184.26,23.77 184.34,23.86 184.63,23.86 184.71,23.95 184.71,24.12 184.63,24.21 184.34,24.21 184.26,24.29 184.26,24.47 184.34,24.55 184.63,24.55 184.71,24.64 184.71,24.81 184.63,24.9 184.34,24.9 184.26,24.99 184.26,25.16 184.34,25.25 184.63,25.25 184.71,25.33 184.71,25.51 184.63,25.59 184.34,25.59 184.26,25.68 184.26,25.85 184.34,25.94 184.63,25.94 184.71,26.03 184.71,26.2 184.63,26.29 184.34,26.29 184.26,26.37 184.26,26.55 184.34,26.63 184.63,26.63 184.71,26.72 184.71,26.89 184.63,26.98 184.34,26.98 184.26,27.07 184.26,27.24 184.34,27.33 184.63,27.33 184.71,27.41 184.71,27.59 184.63,27.67 184.34,27.67 184.26,27.76 184.26,27.93 184.34,28.02 184.63,28.02 184.71,28.1 184.71,28.28 184.63,28.36 184.34,28.36 184.26,28.45 184.26,28.62 184.34,28.71 184.63,28.71 184.71,28.8 184.71,30.81 197.25,43.34 197.77,43.34 199.83,45.4 199.83,51.9 201.91,53.98 201.91,54.85 203.02,55.96 203.02,57.77 202.81,57.98 202.81,59.15 v2(202.45,59.51)
M_B_DQ<53>: length 58.4
  TOP w0.076: U1.AN27 v2(202.45,60.15)
  TOP w0.129: CN1.211 v2(184.87,20.62)
  LAY6 w0.076: v2(202.45,60.15) 202.99,59.61 202.99,58.1 203.21,57.88 203.21,55.82 202.14,54.75 202.14,53.95 200.06,51.86
  LAY6 w0.087: v2(184.87,20.62) 185.57,21.32 185.57,22.74 185.47,22.84 185.22,22.84 185.13,22.92 185.13,23.1 185.22,23.18 185.49,23.18 185.57,23.26 185.57,23.43 185.48,23.52 185.14,23.52 185.06,23.6 185.06,23.78 185.14,23.86 185.48,23.86 185.57,23.95 185.57,24.12 185.48,24.21 185.14,24.21 185.06,24.3 185.06,24.47 185.14,24.56 185.48,24.56 185.57,24.64 185.57,24.82 185.48,24.9 185.14,24.9 185.06,24.99 185.06,25.16 185.14,25.25 185.48,25.25 185.57,25.34 185.57,25.51 185.48,25.6 185.14,25.6 185.06,25.68 185.06,25.86 185.14,25.94 185.48,25.94 185.57,26.03 185.57,26.2 185.48,26.29 185.14,26.29 185.06,26.38 185.06,26.55 185.14,26.63 185.48,26.63 185.57,26.72 185.57,26.89 185.48,26.98 185.14,26.98 185.06,27.07 185.06,27.24 185.14,27.33 185.48,27.33 185.57,27.41 185.57,27.59 185.48,27.67 185.14,27.67 185.06,27.76 185.06,27.93 185.14,28.02 185.48,28.02 185.57,28.11 185.57,28.28 185.48,28.37 185.14,28.37 185.06,28.45 185.06,28.63 185.14,28.71 185.48,28.71 185.57,28.8 185.57,28.97 185.48,29.06 185.14,29.06 185.06,29.15 185.06,29.32 185.14,29.41 185.48,29.41 185.57,29.49 185.57,29.67 185.48,29.75 185.14,29.75 185.06,29.84 185.06,30.01 185.14,30.1 185.48,30.1 185.57,30.19 185.57,31.16 197.43,43.02 197.78,43.02 200.06,45.3 200.06,51.86
M_B_DQ<54>: length 58
  TOP w0.076: U1.AN25 v2(201.53,60.15)
  TOP w0.129: CN1.228 v2(180.61,15.17)
  LAY6 w0.076: 196.92,51.57 198.6,53.25 198.6,53.84 200.8,56.05 200.8,57.91 200.97,58.09 200.97,59.59 v2(201.53,60.15)
  LAY6 w0.087: v2(180.61,15.17) 180.49,15.04 180.22,15.04 179.98,15.28 179.98,17.4 179.65,17.73 179.65,30.59 187.37,38.31 187.37,39.51 189.13,41.27 191.2,41.27 196.92,46.99 196.92,51.57
M_B_DQ<55>: length 57.4
  TOP w0.076: U1.AP25 v2(201.53,59.51)
  TOP w0.129: v2(180.61,16.34) 181.15,16.34 181.61,15.88 CN1.224
  LAY6 w0.076: 197.13,51.3 199.87,54.03 199.87,54.86 200.96,55.96 200.96,57.82 201.15,58.01 201.15,59.13 v2(201.53,59.51)
  LAY6 w0.087: 197.13,51.3 197.13,46.9 191.22,40.98 189.24,40.98 187.66,39.4 187.66,38.12 179.99,30.45 179.99,17.77 180.21,17.55 180.21,16.75 v2(180.61,16.34)
M_B_DQ<56>: length 56.7
  TOP w0.076: U1.AT22 v2(199.7,58.24)
  TOP w0.129: v2(178.36,19.45) 178.75,19.06 179.22,19.06 179.36,19.21 CN1.233
  LAY6 w0.076: v2(199.7,58.24) 199.7,58.11 200.14,57.67 200.14,56.33 198.02,54.22 198.02,53.95 195.62,51.54 195.62,50.76
  LAY6 w0.087: v2(178.36,19.45) 178.6,19.45 178.75,19.59 178.75,21.69 178.66,21.78 178.48,21.78 178.39,21.87 178.39,22.04 178.48,22.13 178.66,22.13 178.75,22.21 178.75,22.39 178.66,22.47 178.48,22.47 178.39,22.56 178.39,22.73 178.48,22.82 178.66,22.82 178.75,22.91 178.75,23.31 178.66,23.4 178.66,23.68 178.57,23.77 178.5,23.77 178.41,23.85 178.41,24.03 178.5,24.11 178.57,24.11 178.66,24.2 178.66,24.37 178.57,24.46 178.5,24.46 178.41,24.55 178.41,24.72 178.5,24.81 178.57,24.81 178.66,24.89 178.66,25.07 178.57,25.15 178.5,25.15 178.41,25.24 178.41,25.41 178.5,25.5 178.57,25.5 178.66,25.59 178.66,31.42 178.95,31.71 179.17,31.71 179.31,31.85 179.31,32.06 179.44,32.2 179.66,32.2 179.8,32.34 179.8,32.55 179.93,32.69 180.15,32.69 180.29,32.83 180.29,33.04 180.42,33.18 180.64,33.18 180.78,33.32 180.78,33.54 180.91,33.67 181.13,33.67 181.27,33.81 181.27,34.03 181.4,34.16 181.62,34.16 181.76,34.3 181.76,34.52 181.89,34.65 182.11,34.65 182.25,34.79 182.25,35.01 182.38,35.14 182.6,35.14 182.74,35.28 182.74,35.5 182.87,35.63 183.09,35.63 183.23,35.77 183.23,35.99 183.36,36.12 183.58,36.12 183.72,36.26 183.72,36.48 184.03,36.79 184.27,36.79 186.11,38.63 186.11,39.67 190.71,44.27 191.85,44.27 195.62,48.04 195.62,50.76
M_B_DQ<57>: length 56.2
  TOP w0.076: U1.AU22 v2(199.7,57.59)
  TOP w0.129: CN1.237 v2(178.36,20.62)
  LAY6 w0.076: v2(199.7,57.59) 199.8,57.5 199.8,56.26 197.85,54.31 197.85,54.02 195.43,51.61 195.43,50.86
  LAY6 w0.087: 195.43,50.86 195.43,48.38 191.69,44.64 190.66,44.64 185.42,39.4 185.42,39.28 185.82,38.89 185.82,38.76 185.69,38.64 185.57,38.64 185.18,39.03 185.06,39.03 184.93,38.91 184.93,38.79 185.33,38.4 185.33,38.27 185.2,38.15 185.08,38.15 184.69,38.54 184.57,38.54 184.44,38.42 184.44,38.3 184.83,37.91 184.83,37.78 184.71,37.66 184.59,37.66 184.2,38.05 184.08,38.05 183.95,37.93 183.95,37.81 184.34,37.42 184.34,37.29 184.22,37.17 184.1,37.17 183.71,37.56 183.59,37.56 183.36,37.33 183.36,36.63 178.07,31.35 178.07,30.78 178.16,30.7 178.26,30.7 178.35,30.61 178.35,30.44 178.26,30.35 178.16,30.35 178.07,30.26 178.07,30.09 178.16,30 178.26,30 178.35,29.92 178.35,29.74 178.26,29.66 178.16,29.66 178.07,29.57 178.07,29.4 178.16,29.31 178.26,29.31 178.35,29.22 178.35,29.05 178.26,28.96 178.16,28.96 178.07,28.88 178.07,28.7 178.16,28.62 178.26,28.62 178.35,28.53 178.35,28.36 178.26,28.27 178.16,28.27 178.07,28.18 178.07,28.01 178.16,27.93 178.26,27.93 178.35,27.84 178.35,27.67 178.26,27.58 178.16,27.58 178.07,27.49 178.07,27.32 178.16,27.23 178.26,27.23 178.35,27.15 178.35,26.97 178.26,26.89 178.16,26.89 178.07,26.8 178.07,26.63 178.16,26.54 178.26,26.54 178.35,26.45 178.35,26.28 178.26,26.19 178.16,26.19 178.07,26.11 178.07,20.91 v2(178.36,20.62)
M_B_DQ<58>: length 55.2
  TOP w0.076: U1.AU21 v2(198.79,57.59)
  TOP w0.129: CN1.250 v2(175.11,15.17)
  LAY6 w0.076: 193.3,50.12 193.3,51.48 198.56,56.75 198.56,57.37 v2(198.79,57.59)
  LAY6 w0.087: v2(175.11,15.17) 175.77,15.17 176.45,15.85 176.45,24.33 176.34,24.43 176.34,27.14 176.79,27.58 176.79,31.9 181.51,36.63 181.51,37.65 189.26,45.4 190.18,45.4 193.3,48.52 193.3,50.12
M_B_DQ<59>: length 56.1
  TOP w0.076: U1.AT21 v2(198.79,58.24)
  TOP w0.129: v2(175.11,16.34) 175.29,16.34 176.11,15.52 CN1.246
  LAY6 w0.076: 193.06,51.51 196.61,55.05 196.61,55.12 198.32,56.83 198.32,57.7 198.79,58.16 v2(198.79,58.24)
  LAY6 w0.087: 193.06,51.51 193.06,49.08 192.38,48.4 191.81,48.4 189.96,46.55 189.82,46.55 189.27,46.01 189.27,45.77 181.17,37.66 181.17,36.71 176.48,32.03 176.48,29.08 175.84,28.43 175.84,23.66 176.21,23.29 176.21,17.43 v2(175.11,16.34)
M_B_DQ<60>: length 58.2
  TOP w0.076: v2(199.7,60.15) U1.AN22
  TOP w0.129: CN1.236 178.61,15.25 v2(179.11,15.75)
  LAY6 w0.076: v2(199.7,60.15) 200.25,59.61 200.25,58.09 200.52,57.81 200.52,56.07 198.39,53.95 198.39,53.79 196.61,52.01
  LAY6 w0.087: 196.61,52.01 196.04,51.44 196.04,47.6 192.03,43.58 190.92,43.58 190.73,43.38 190.73,43.26 191.02,42.97 191.02,42.85 190.89,42.73 190.77,42.73 190.48,43.02 190.36,43.02 186.87,39.53 186.87,38.48 179.33,30.94 179.33,17.55 179.55,17.33 179.55,16.09 179.21,15.75 v2(179.11,15.75)
M_B_DQ<61>: length 57.9
  TOP w0.076: U1.AP22 v2(199.7,59.51)
  TOP w0.129: CN1.232 179.61,16.42 v2(179.11,16.92)
  LAY6 w0.076: 195.84,50.63 195.84,51.49 198.2,53.86 198.2,54.11 200.31,56.22 200.31,57.74 200.08,57.97 200.08,59.14 v2(199.7,59.51)
  LAY6 w0.087: 195.84,50.63 195.84,47.79 192,43.95 190.82,43.95 189.2,42.32 186.43,39.56 186.43,38.48 179.01,31.06 179.01,18.76 178.2,17.94 178.2,16.81 178.4,16.61 178.8,16.61 v2(179.11,16.92)
M_B_DQ<62>: length 56.9
  TOP w0.076: U1.AP21 v2(198.79,59.51)
  TOP w0.129: v2(175.36,19.45) 176.36,20.45 CN1.245
  LAY6 w0.076: v2(198.79,59.51) 198.4,59.12 198.4,58.01 198.09,57.7 198.09,56.83 196.53,55.28 196.5,55.28 192.83,51.61 192.83,50.96
  LAY6 w0.087: v2(175.36,19.45) 175.87,19.96 175.87,23.11 175.51,23.48 175.51,29.3 175.59,29.38 176.07,29.38 176.15,29.47 176.15,29.64 176.07,29.73 175.59,29.73 175.51,29.82 175.51,29.99 175.59,30.08 176.07,30.08 176.15,30.16 176.15,30.34 176.07,30.42 175.59,30.42 175.51,30.51 175.51,30.68 175.59,30.77 176.07,30.77 176.15,30.86 176.15,31.03 176.07,31.12 175.59,31.12 175.51,31.2 175.51,31.52 180.84,36.85 180.84,37.74 189.03,45.93 189.03,46.05 191.41,48.42 191.41,49.54 192.83,50.96
M_B_DQ<63>: length 58
  TOP w0.076: U1.AN21 v2(198.79,60.15)
  TOP w0.129: CN1.249 v2(175.36,20.62)
  LAY6 w0.076: v2(198.79,60.15) 198.79,60.15 198.23,59.58 198.23,58.07 197.86,57.71 197.86,56.84 196.57,55.55 196.45,55.55 192.64,51.74
  LAY6 w0.087: 192.64,51.74 192.64,51.06 191.23,49.65 191.23,48.6 188.45,45.82 188.45,45.7 180.54,37.79 180.54,37.02 179.21,35.69 179.05,35.69 178.91,35.82 178.79,35.82 178.66,35.7 178.66,35.58 178.84,35.4 178.84,35.32 178.72,35.2 178.59,35.2 178.29,35.5 178.17,35.5 178.05,35.38 178.05,35.25 178.35,34.95 178.35,34.83 178.23,34.71 178.1,34.71 177.8,35.01 177.68,35.01 177.56,34.89 177.56,34.76 177.86,34.46 177.86,34.34 177.74,34.22 177.61,34.22 177.31,34.52 177.19,34.52 177.06,34.4 177.06,34.27 177.37,33.97 177.37,33.85 177.25,33.73 177.12,33.73 176.82,34.03 176.7,34.03 176.57,33.91 176.57,33.78 176.88,33.48 176.88,33.36 176.76,33.24 176.63,33.24 176.33,33.54 176.21,33.54 176.08,33.42 176.08,33.29 176.39,32.99 176.39,32.87 176.26,32.75 176.14,32.75 175.84,33.05 175.72,33.05 175.59,32.93 175.59,32.8 175.9,32.5 175.9,32.38 175.19,31.67 175.19,20.79 v2(175.36,20.62)
M_B_DQS_DN*<0>: length 59.5
  TOP w0.076: U1.BA38 207.93,55.97 207.93,56.08 208.07,56.13 208.15,56.13 208.2,56.05 208.25,55.97 208.28,55.91 208.28,55.69 208.24,55.61 208.24,55.33 208.3,55.2 208.3,55.08 208.24,54.97 208.24,54.47 208.38,54.34 208.38,53.99 208.2,53.81 208.2,52.66 208.36,52.5 208.36,50.24 208.22,50.1 208.01,50.1 207.97,50.14 v2(207.97,50.28)
  TOP w0.114: CN1.11 236.87,21.1 236.76,20.99 236.76,19.98 236.45,19.66 236.08,19.66 v2(235.86,19.45)
  LAY3 w0.094: v2(207.97,50.28) 207.81,50.13 207.45,50.13 207.2,49.88 207.2,48.68 207.39,48.48 207.39,45.92 207.43,45.88 207.43,45.72 207.44,45.7 207.44,45.06 216.08,36.42 222.94,36.42 223.32,36.04 234.97,24.39 234.97,23.13 235.17,22.93 235.43,22.93 235.52,22.83 235.52,22.65 235.43,22.55 235.17,22.55 234.97,22.35 234.97,22.01 235.17,21.81 235.39,21.81 235.48,21.72 235.48,21.53 235.39,21.44 235.17,21.44 234.97,21.23 234.97,19.8 235.32,19.45 v2(235.86,19.45)
M_B_DQS_DN*<1>: length 60.9
  TOP w0.076: U1.AY34 205.56,56.26 205.54,56.24 205.48,56.24 205.35,56.19 205.27,56.05 205.23,55.94 205.23,55.66 205.26,55.58 205.26,55.37 205.21,55.26 205.21,55.04 205.26,54.93 205.26,53.91 205.13,53.78 205.13,48.31 204.92,48.1 204.64,48.1 v2(204.41,48.33)
  TOP w0.114: CN1.32 231.61,14.92 231.47,15.06 231.47,15.84 231.13,16.18 230.77,16.18 v2(230.61,16.33)
  LAY3 w0.076: v2(204.41,48.33) 204.6,48.14 204.8,48.14 205.03,47.92 205.03,45.33 204.52,44.83 204.52,43.96 204.53,43.95 204.53,43.9 204.54,43.89 204.54,43.88
  LAY3 w0.094: 204.54,43.88 204.54,42.17 210.31,36.4 210.33,36.4 210.38,36.35 210.38,36.33 214.81,31.9 222.01,31.9 230.18,23.73 230.18,19.22 229.93,18.97 229.93,16.26 230.05,16.14 230.42,16.14 v2(230.61,16.33)
M_B_DQS_DN*<2>: length 52.8
  TOP w0.076: U1.AT38 v2(208.85,58.24)
  TOP w0.114: CN1.177 193.36,20.28 v2(193.45,20.19)
  LAY6 w0.076: v2(208.85,58.24) 208.85,58.34 208.77,58.42 208.66,58.42 208.49,58.25 208.49,57.19 208.51,57.16 208.51,53.88 207.02,52.38
  LAY6 w0.094: v2(193.45,20.19) 193.45,20.37 193.29,20.53 193.12,20.53 192.96,20.68 192.96,24.68 193.06,24.78 193.42,24.78 193.63,24.99 193.63,25.34 193.42,25.55 193.06,25.55 192.96,25.64 192.96,25.83 193.06,25.92 193.42,25.92 193.63,26.13 193.63,26.48 193.42,26.69 193.06,26.69 192.96,26.78 192.96,26.97 193.06,27.06 193.42,27.06 193.63,27.27 193.63,27.62 193.42,27.83 193.06,27.83 192.96,27.93 192.96,28.47 193.47,28.98 193.61,28.98 193.7,28.88 193.99,28.88 194.24,29.13 194.24,29.43 194.15,29.52 194.15,29.65 194.28,29.78 194.41,29.78 194.51,29.69 194.8,29.69 195.05,29.94 195.05,30.24 194.96,30.33 194.96,30.46 195.09,30.59 195.22,30.59 195.32,30.5 195.61,30.5 195.86,30.75 195.86,31.04 195.77,31.14 195.77,31.27 195.9,31.4 196.03,31.4 196.16,31.27 196.42,31.27 196.67,31.52 196.67,31.85 196.58,31.95 196.58,32.08 199.01,34.51 199.01,36.18 207.01,44.18 207.01,52.38 207.02,52.38
M_B_DQS_DN*<3>: length 55
  TOP w0.076: U1.AT32 v2(205.19,58.24)
  TOP w0.114: v2(187.11,16.34) 187.35,16.1 187.7,16.1 187.98,15.83 187.98,13.93 CN1.198
  LAY6 w0.076: 202.94,46.62 202.94,52.52 203.75,53.33 203.75,54.53 204.96,55.73 204.96,56.67 204.98,56.69 204.98,56.74 205.57,57.33 205.57,58.41 205.47,58.5 205.21,58.5 205.15,58.44 205.15,58.28 v2(205.19,58.24)
  LAY6 w0.094: 202.94,46.62 202.94,45.16 198.85,41.07 198.3,41.07 188.52,31.28 188.52,24.9 188.53,24.89 188.53,23.71 188.53,23.71 188.53,17.2 187.49,16.16 187.3,16.16 v2(187.11,16.34)
M_B_DQS_DN*<4>: length 58.8
  TOP w0.076: U1.BA30 202.98,55.98 203,56.12 203.15,56.15 203.2,56.09 203.27,55.97 203.3,55.91 203.3,55.69 203.26,55.61 203.26,55.33 203.32,55.2 203.32,55.1 203.32,55.08 203.26,54.97 203.26,54.25 203.29,54.22 203.29,53.82 203.29,53.82 202.92,53.45 202.92,50.33 202.83,50.24 202.57,50.24 v2(202.53,50.28)
  TOP w0.114: CN1.53 226.37,21.01 226.31,20.95 226.31,19.95 226,19.64 225.56,19.64 v2(225.37,19.45)
  LAY3 w0.076: v2(202.53,50.28) 202.45,50.2 201.93,50.2 201.72,49.99 201.72,46.09 201.91,45.89 201.91,45.33 200.96,44.37 200.96,43.79 200.97,43.78
  LAY3 w0.094: 200.97,43.78 200.97,39.36 204.15,36.18 212.29,28.03 212.91,28.03 213,27.94 213,27.66 213.21,27.45 213.56,27.45 213.77,27.66 213.77,27.94 213.86,28.03 214.05,28.03 214.15,27.94 214.15,27.66 214.35,27.45 214.7,27.45 214.91,27.66 214.91,27.94 215.01,28.03 220.11,28.03 224.28,23.86 224.28,23.85 224.51,23.62 224.51,23.44 224.52,23.43 224.52,19.69 224.77,19.45 v2(225.37,19.45)
